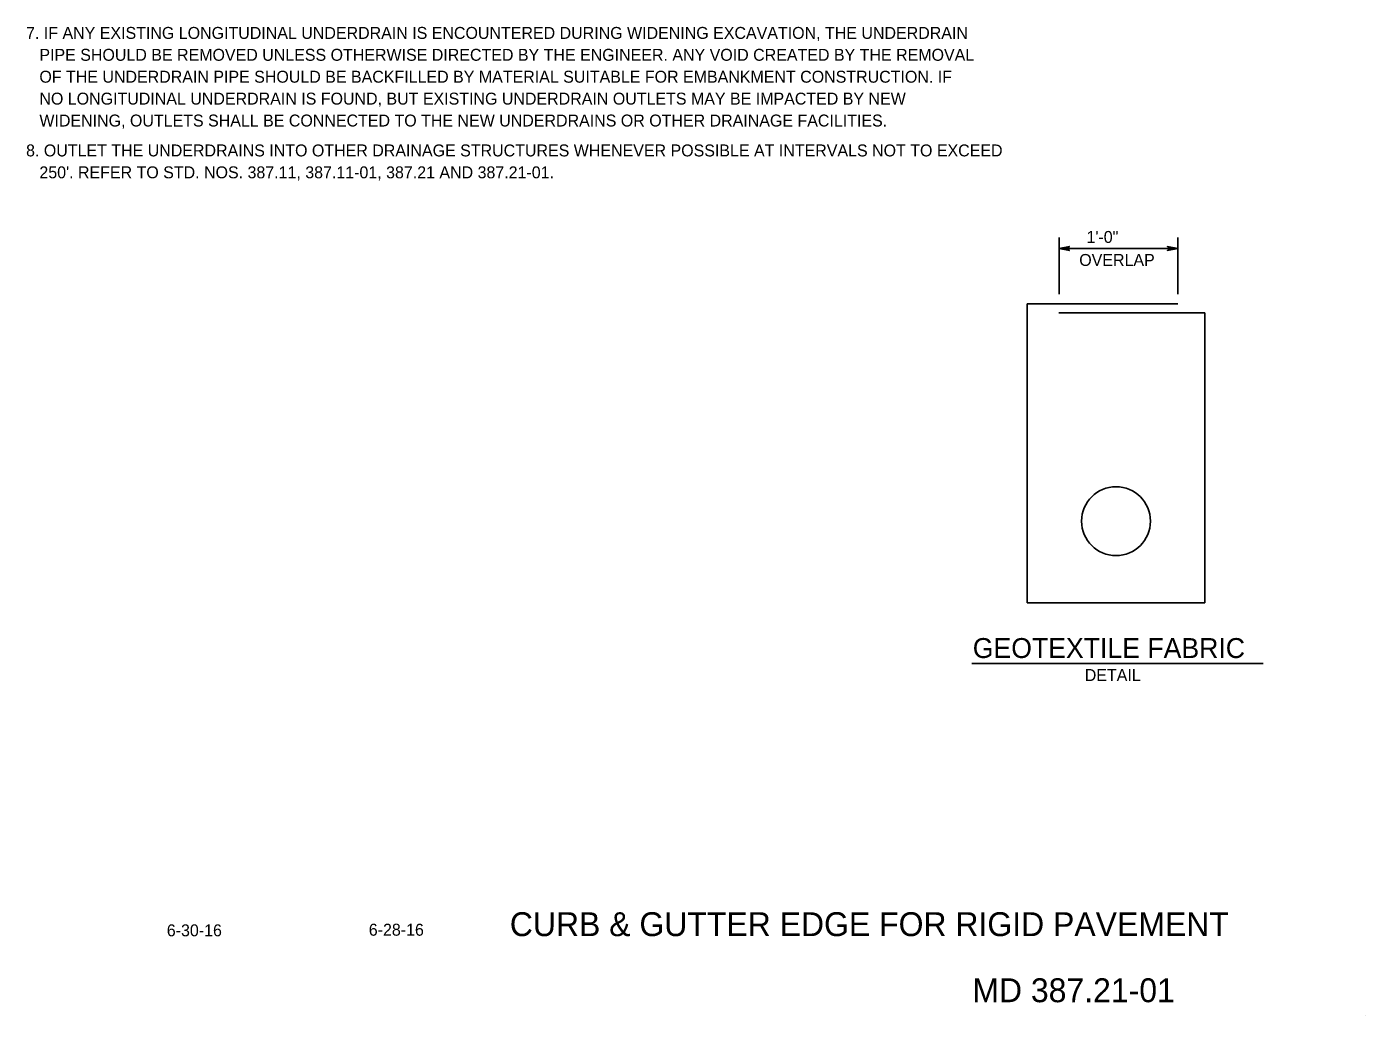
# Model space of a CAD drawing. Extents: x -0.97 to 5.98, y -2.63 to 7.27.
# Drawn here: x -0.74 to 5.98, y -2.63 to 2.34 of the extents above; entities that cross this region are included whole.
import ezdxf

# ---------------------------------------------------------------- set-up
doc = ezdxf.new("R2010")
doc.units = 0
for name, color, linetype in [('DETL-DIMS', 7, 'Continuous'), ('DETL-LINE', 7, 'Continuous'), ('DETL-NOTE', 7, 'Continuous'), ('DETL-TITL', 7, 'Continuous'), ('TTLB-TEXT', 7, 'Continuous')]:
    doc.layers.add(name, color=color, linetype=linetype)

msp = doc.modelspace()

# ---------------------------------------------------------------- linework, layer by layer
at = {"layer": 'DETL-DIMS'}
for p, q in [((4.4435, 1.28), (4.4435, 0.9944)), ((5.0395, 1.28), (5.0395, 0.9944)), ((4.4435, 1.2244), (5.0395, 1.2244))]:
    msp.add_line(p, q, dxfattribs=at)
for points in [[(4.4435, 1.2244), (4.4953, 1.2341), (4.4913, 1.2314), (4.4892, 1.2279), (4.4886, 1.2244), (4.4892, 1.2209), (4.4913, 1.2175), (4.4953, 1.2147), (4.4435, 1.2244), (4.4913, 1.2175), (4.4892, 1.2209), (4.4435, 1.2244), (4.4886, 1.2244), (4.4892, 1.2279), (4.4435, 1.2244), (4.4913, 1.2314)], [(5.0395, 1.2244), (4.9878, 1.2147), (4.9917, 1.2175), (4.9938, 1.2209), (4.9944, 1.2244), (4.9938, 1.2279), (4.9917, 1.2314), (4.9878, 1.2341), (5.0395, 1.2244), (4.9917, 1.2314), (4.9938, 1.2279), (5.0395, 1.2244), (4.9944, 1.2244), (4.9938, 1.2209), (5.0395, 1.2244), (4.9917, 1.2175)]]:
    msp.add_lwpolyline(points, dxfattribs=at)
at = {"layer": 'DETL-LINE'}
for p, q in [((4.2838, -0.5555), (4.2838, 0.9466)), ((4.2838, 0.9466), (5.0395, 0.9466)), ((5.175, 0.901), (4.4418, 0.901)), ((5.175, 0.901), (5.175, -0.5555)), ((4.2838, -0.5556), (5.175, -0.5549))]:
    msp.add_line(p, q, dxfattribs=at)
msp.add_circle((4.7294, -0.1449), 0.173, dxfattribs=at)
at = {"layer": 'DETL-TITL'}
msp.add_line((4.0054, -0.8599), (5.469, -0.8599), dxfattribs=at)
at = {"layer": 'TTLB-TEXT'}
msp.add_line((5.9809, -2.6259), (5.9809, -2.6259), dxfattribs=at)

# ---------------------------------------------------------------- texts
at = {"layer": 'DETL-NOTE'}
for s, p in [('7. IF ANY EXISTING LONGITUDINAL UNDERDRAIN IS ENCOUNTERED DURING WIDENING EXCAVATION, THE UNDERDRAIN ', (-0.7443, 2.2768)), ('   PIPE SHOULD BE REMOVED UNLESS OTHERWISE DIRECTED BY THE ENGINEER. ANY VOID CREATED BY THE REMOVAL ', (-0.7443, 2.1668)), ('   OF THE UNDERDRAIN PIPE SHOULD BE BACKFILLED BY MATERIAL SUITABLE FOR EMBANKMENT CONSTRUCTION. IF ', (-0.7443, 2.0568)), ('   NO LONGITUDINAL UNDERDRAIN IS FOUND, BUT EXISTING UNDERDRAIN OUTLETS MAY BE IMPACTED BY NEW ', (-0.7443, 1.9468)), ('   WIDENING, OUTLETS SHALL BE CONNECTED TO THE NEW UNDERDRAINS OR OTHER DRAINAGE FACILITIES.', (-0.7443, 1.8368)), ('8. OUTLET THE UNDERDRAINS INTO OTHER DRAINAGE STRUCTURES WHENEVER POSSIBLE AT INTERVALS NOT TO EXCEED ', (-0.7443, 1.6866)), ("   250'. REFER TO STD. NOS. 387.11, 387.11-01, 387.21 AND 387.21-01.", (-0.7443, 1.5766)), ('1\'-0"', (4.5811, 1.2522)), ('OVERLAP', (4.5447, 1.1366)), ('DETAIL', (4.5724, -0.9477))]:
    msp.add_text(s, height=0.06, dxfattribs=at).set_placement(p)
at = {"layer": 'DETL-TITL'}
msp.add_text('GEOTEXTILE FABRIC', height=0.1, dxfattribs=at).set_placement((4.0099, -0.8321))
at = {"layer": 'TTLB-TEXT'}
for s, height, p in [('CURB & GUTTER EDGE FOR RIGID PAVEMENT', 0.12, (1.685, -2.2287)), ('6-30-16', 0.06, (-0.0375, -2.2296)), ('6-28-16', 0.06, (0.9768, -2.2266)), ('MD 387.21-01', 0.12, (4.0078, -2.5605))]:
    msp.add_text(s, height=height, dxfattribs=at).set_placement(p)

doc.saveas('drawing.dxf')
